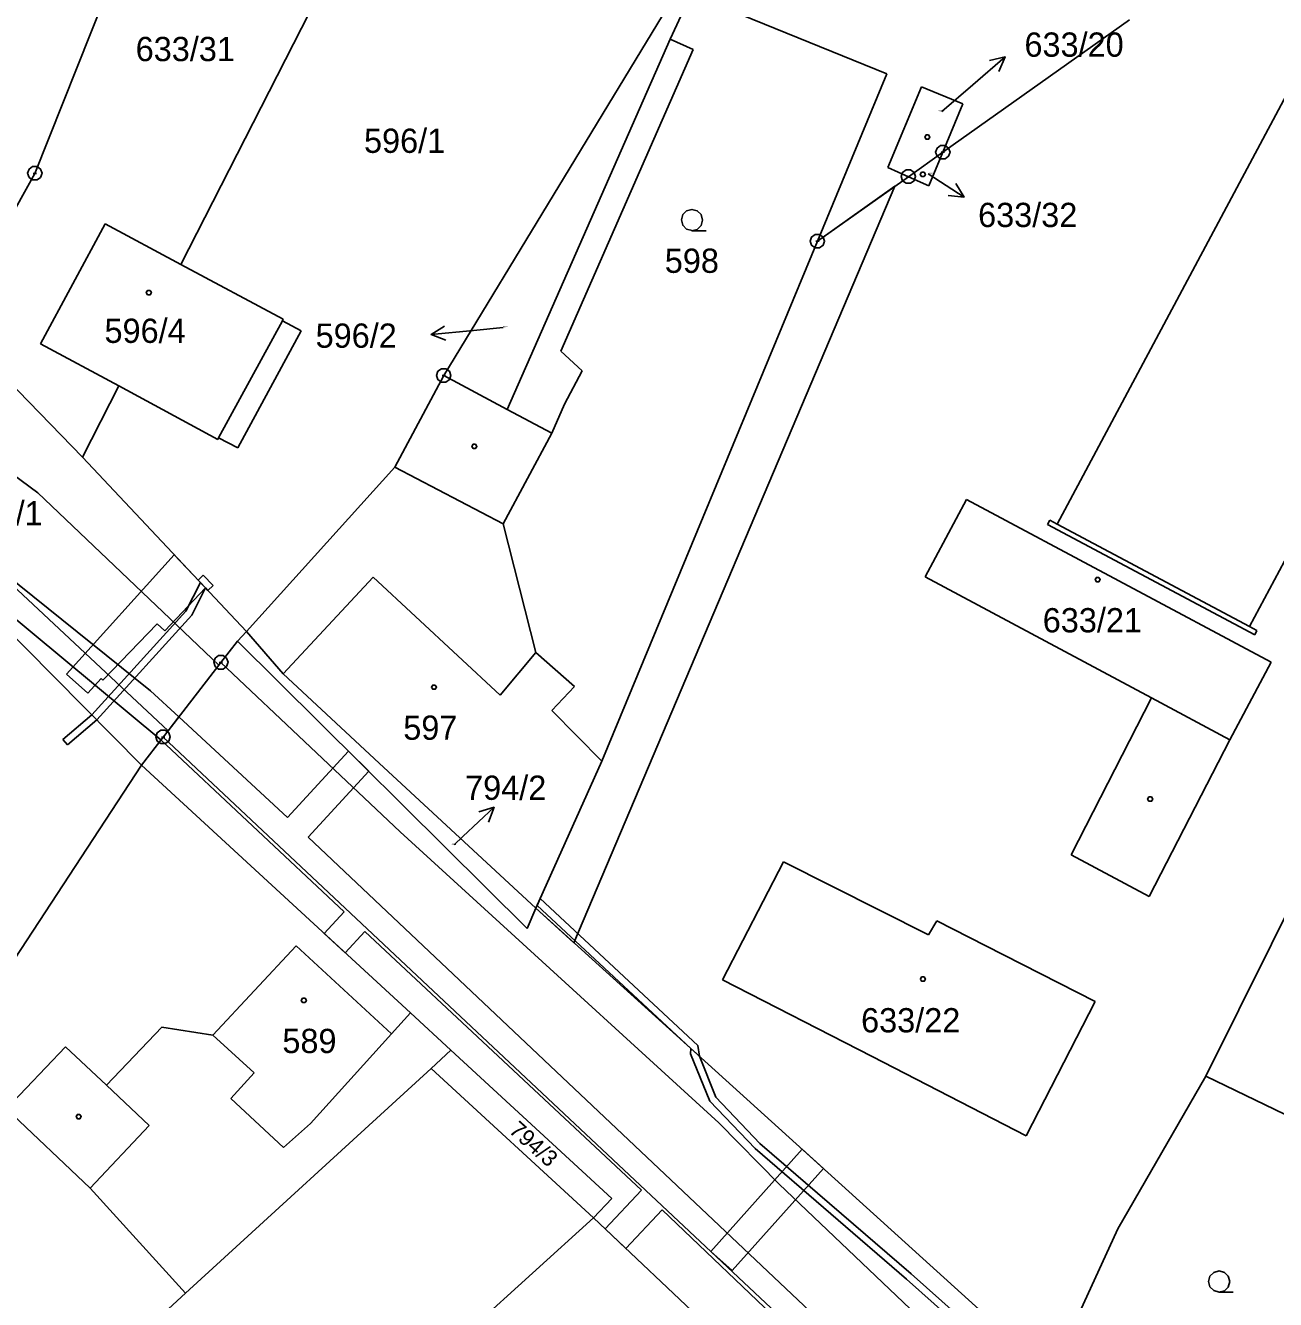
# Model space of a CAD drawing. Extents: x -759060 to -757386, y -1172273 to -1170948.
# Drawn here: x -758335.3 to -758247.7, y -1171458.9 to -1171369.6 of the extents above; entities that cross this region are included whole.
import ezdxf

# ---------------------------------------------------------------- set-up
doc = ezdxf.new("R2010")
doc.units = 0
for name, color, linetype in [('Vrstva 1', 7, 'Continuous'), ('Vrstva 12', 7, 'Continuous'), ('Vrstva 13', 7, 'Continuous'), ('Vrstva 2', 7, 'Continuous'), ('Vrstva 3', 7, 'Continuous'), ('Vrstva 4', 7, 'Continuous'), ('Vrstva 5', 7, 'Continuous'), ('Vrstva 7', 7, 'Continuous'), ('Vrstva 8', 7, 'Continuous')]:
    doc.layers.add(name, color=color, linetype=linetype)

msp = doc.modelspace()

# ---------------------------------------------------------------- linework, layer by layer
at = {"layer": 'Vrstva 1'}
for p, q in [((-758263.01, -1171404.59), (-758220.74, -1171325.36)), ((-758207.32, -1171332.5), (-758249.54, -1171411.77)), ((-758323.66, -1171352.29), (-758334.67, -1171380)), ((-758324.43, -1171386.38), (-758310.09, -1171358.28)), ((-758306.01, -1171394.17), (-758289.56, -1171367.06)), ((-758288.68, -1171367.44), (-758290.15, -1171370.6)), ((-758288.68, -1171367.44), (-758274.95, -1171373.03)), ((-758271.03, -1171378.52), (-758257.96, -1171369.23)), ((-758301.56, -1171396.55), (-758290.15, -1171370.6)), ((-758297.8, -1171392.45), (-758288.53, -1171371.32)), ((-758290.15, -1171370.6), (-758288.53, -1171371.32)), ((-758274.95, -1171373.03), (-758279.82, -1171384.76)), ((-758274.9, -1171379.58), (-758272.52, -1171373.92)), ((-758272.52, -1171373.92), (-758269.63, -1171375.13)), ((-758269.63, -1171375.13), (-758271.03, -1171378.52)), ((-758273.45, -1171380.23), (-758271.03, -1171378.52)), ((-758271.03, -1171378.52), (-758272.01, -1171380.88)), ((-758340.5, -1171390.47), (-758334.67, -1171380)), ((-758279.82, -1171384.76), (-758273.45, -1171380.23)), ((-758273.45, -1171380.23), (-758274.9, -1171379.58)), ((-758272.01, -1171380.88), (-758273.45, -1171380.23)), ((-758334.27, -1171391.95), (-758329.74, -1171383.54)), ((-758329.74, -1171383.54), (-758324.43, -1171386.38)), ((-758279.82, -1171384.76), (-758294.93, -1171421.2)), ((-758324.43, -1171386.38), (-758317.26, -1171390.22)), ((-758340.5, -1171390.47), (-758331.33, -1171399.89)), ((-758317.26, -1171390.22), (-758317.32, -1171390.33)), ((-758317.32, -1171390.33), (-758316, -1171391.03)), ((-758316, -1171391.03), (-758320.45, -1171399.24)), ((-758328.79, -1171394.9), (-758334.27, -1171391.95)), ((-758296.31, -1171393.84), (-758297.8, -1171392.45)), ((-758309.44, -1171400.58), (-758306.01, -1171394.17)), ((-758301.56, -1171396.55), (-758306.01, -1171394.17)), ((-758297.54, -1171396.18), (-758296.31, -1171393.84)), ((-758331.33, -1171399.89), (-758328.79, -1171394.9)), ((-758321.85, -1171398.64), (-758328.79, -1171394.9)), ((-758297.54, -1171396.18), (-758298.45, -1171398.21)), ((-758321.79, -1171398.53), (-758321.85, -1171398.64)), ((-758320.45, -1171399.24), (-758321.79, -1171398.53)), ((-758298.45, -1171398.21), (-758301.84, -1171404.57)), ((-758331.33, -1171399.89), (-758319.84, -1171412.11)), ((-758319.84, -1171412.11), (-758309.44, -1171400.58)), ((-758269.37, -1171402.85), (-758272.27, -1171408.28)), ((-758248.03, -1171414.27), (-758269.37, -1171402.85)), ((-758263.69, -1171404.6), (-758263.53, -1171404.31)), ((-758263.53, -1171404.31), (-758263.01, -1171404.59)), ((-758301.84, -1171404.57), (-758299.57, -1171413.59)), ((-758249.17, -1171412.34), (-758263.69, -1171404.6)), ((-758340.57, -1171407.96), (-758327.2, -1171421.47)), ((-758272.27, -1171408.28), (-758256.4, -1171416.77)), ((-758320.47, -1171412.78), (-758319.84, -1171412.11)), ((-758319.84, -1171412.11), (-758317.28, -1171415.08)), ((-758249.54, -1171411.77), (-758249.02, -1171412.05)), ((-758249.02, -1171412.05), (-758249.17, -1171412.34)), ((-758321.63, -1171414.28), (-758320.47, -1171412.78)), ((-758300.16, -1171432.92), (-758320.47, -1171412.78)), ((-758299.57, -1171413.59), (-758296.86, -1171415.96)), ((-758325.34, -1171419.07), (-758321.77, -1171414.46)), ((-758321.77, -1171414.46), (-758321.63, -1171414.28)), ((-758309.07, -1171426.15), (-758321.63, -1171414.28)), ((-758317.28, -1171415.08), (-758310.54, -1171421.35)), ((-758250.93, -1171419.7), (-758248.03, -1171414.27)), ((-758296.86, -1171415.96), (-758298.44, -1171417.64)), ((-758256.4, -1171416.77), (-758262.04, -1171427.76)), ((-758298.44, -1171417.64), (-758294.93, -1171421.2)), ((-758327.2, -1171421.47), (-758325.68, -1171419.51)), ((-758325.68, -1171419.51), (-758325.34, -1171419.07)), ((-758325.68, -1171419.51), (-758307.9, -1171436.22)), ((-758256.57, -1171430.68), (-758250.93, -1171419.7)), ((-758294.93, -1171421.2), (-758299.56, -1171431.51)), ((-758327.2, -1171421.47), (-758344.49, -1171447.89)), ((-758327.2, -1171421.47), (-758308.34, -1171438.85)), ((-758310.54, -1171421.35), (-758299.56, -1171431.51)), ((-758303.15, -1171431.56), (-758309.07, -1171426.15)), ((-758244.03, -1171426.01), (-758252.61, -1171443.29)), ((-758286.47, -1171436.53), (-758282.2, -1171428.25)), ((-758282.2, -1171428.25), (-758272.03, -1171433.38)), ((-758262.04, -1171427.76), (-758256.57, -1171430.68)), ((-758286.73, -1171446.54), (-758303.15, -1171431.56)), ((-758299.56, -1171431.51), (-758300.16, -1171432.92)), ((-758299.56, -1171431.51), (-758263.45, -1171464.18)), ((-758272.03, -1171433.38), (-758271.46, -1171432.39)), ((-758271.46, -1171432.39), (-758268.01, -1171434.15)), ((-758316.35, -1171434.14), (-758322.21, -1171440.4)), ((-758309.68, -1171440.3), (-758316.35, -1171434.14)), ((-758268.01, -1171434.15), (-758260.36, -1171438.05)), ((-758307.9, -1171436.22), (-758278, -1171464.29)), ((-758275.99, -1171441.91), (-758286.47, -1171436.53)), ((-758260.36, -1171438.05), (-758265.19, -1171447.47)), ((-758309.68, -1171440.3), (-758308.34, -1171438.85)), ((-758308.34, -1171438.85), (-758305.51, -1171441.46)), ((-758325.77, -1171439.84), (-758329.65, -1171443.92)), ((-758322.21, -1171440.4), (-758325.77, -1171439.84)), ((-758336.65, -1171445.58), (-758332.53, -1171441.22)), ((-758332.53, -1171441.22), (-758329.65, -1171443.92)), ((-758305.51, -1171441.46), (-758306.9, -1171442.74)), ((-758305.51, -1171441.46), (-758294.24, -1171451.85)), ((-758306.9, -1171442.74), (-758324.11, -1171458.49)), ((-758306.9, -1171442.74), (-758295.51, -1171453.22)), ((-758265.19, -1171447.47), (-758275.99, -1171441.91)), ((-758252.61, -1171443.29), (-758258.78, -1171453.97)), ((-758224.39, -1171456.86), (-758252.61, -1171443.29)), ((-758330.8, -1171451.14), (-758336.65, -1171445.58)), ((-758282.5, -1171450.86), (-758286.73, -1171446.54)), ((-758330.8, -1171451.14), (-758324.11, -1171458.49)), ((-758271.69, -1171461.13), (-758282.5, -1171450.86)), ((-758295.51, -1171453.22), (-758294.24, -1171451.85)), ((-758295.51, -1171453.22), (-758322.51, -1171477.63)), ((-758276.72, -1171470.98), (-758295.51, -1171453.22)), ((-758258.78, -1171453.97), (-758263.45, -1171464.18)), ((-758324.11, -1171458.49), (-758343.02, -1171475.78))]:
    msp.add_line(p, q, dxfattribs=at)
at = {"layer": 'Vrstva 12'}
for p, q in [((-758263.01, -1171404.59), (-758220.74, -1171325.36)), ((-758207.32, -1171332.5), (-758249.54, -1171411.77)), ((-758274.9, -1171379.58), (-758272.52, -1171373.92)), ((-758272.52, -1171373.92), (-758269.63, -1171375.13)), ((-758269.63, -1171375.13), (-758271.03, -1171378.52)), ((-758271.03, -1171378.52), (-758272.01, -1171380.88)), ((-758273.45, -1171380.23), (-758274.9, -1171379.58)), ((-758272.01, -1171380.88), (-758273.45, -1171380.23)), ((-758334.27, -1171391.95), (-758329.74, -1171383.54)), ((-758329.74, -1171383.54), (-758324.43, -1171386.38)), ((-758324.43, -1171386.38), (-758317.26, -1171390.22)), ((-758321.79, -1171398.53), (-758317.32, -1171390.33)), ((-758317.26, -1171390.22), (-758317.32, -1171390.33)), ((-758328.79, -1171394.9), (-758334.27, -1171391.95)), ((-758321.85, -1171398.64), (-758328.79, -1171394.9)), ((-758321.79, -1171398.53), (-758321.85, -1171398.64)), ((-758269.37, -1171402.85), (-758272.27, -1171408.28)), ((-758248.03, -1171414.27), (-758269.37, -1171402.85)), ((-758263.01, -1171404.59), (-758249.54, -1171411.77)), ((-758310.95, -1171408.29), (-758317.28, -1171415.08)), ((-758302.06, -1171416.57), (-758310.95, -1171408.29)), ((-758272.27, -1171408.28), (-758256.4, -1171416.77)), ((-758299.57, -1171413.59), (-758302.06, -1171416.57)), ((-758299.57, -1171413.59), (-758296.86, -1171415.96)), ((-758317.28, -1171415.08), (-758310.54, -1171421.35)), ((-758250.93, -1171419.7), (-758248.03, -1171414.27)), ((-758296.86, -1171415.96), (-758298.44, -1171417.64)), ((-758256.4, -1171416.77), (-758250.93, -1171419.7)), ((-758298.44, -1171417.64), (-758294.93, -1171421.2)), ((-758294.93, -1171421.2), (-758299.56, -1171431.51)), ((-758310.54, -1171421.35), (-758299.56, -1171431.51)), ((-758286.47, -1171436.53), (-758282.2, -1171428.25)), ((-758282.2, -1171428.25), (-758272.03, -1171433.38)), ((-758272.03, -1171433.38), (-758271.46, -1171432.39)), ((-758271.46, -1171432.39), (-758268.01, -1171434.15)), ((-758316.35, -1171434.14), (-758322.21, -1171440.4)), ((-758309.68, -1171440.3), (-758316.35, -1171434.14)), ((-758268.01, -1171434.15), (-758260.36, -1171438.05)), ((-758275.99, -1171441.91), (-758286.47, -1171436.53)), ((-758260.36, -1171438.05), (-758265.19, -1171447.47)), ((-758322.21, -1171440.4), (-758319.29, -1171443.05)), ((-758315.36, -1171446.6), (-758309.68, -1171440.3)), ((-758265.19, -1171447.47), (-758275.99, -1171441.91)), ((-758319.29, -1171443.05), (-758320.94, -1171444.84)), ((-758320.94, -1171444.84), (-758317.24, -1171448.28)), ((-758317.24, -1171448.28), (-758315.36, -1171446.6))]:
    msp.add_line(p, q, dxfattribs=at)
at = {"layer": 'Vrstva 13'}
for p, q in [((-758274.39, -1171380.9), (-758296.89, -1171433.93)), ((-758279.82, -1171384.76), (-758274.39, -1171380.9)), ((-758294.93, -1171421.2), (-758279.82, -1171384.76)), ((-758332.45, -1171415.1), (-758324.9, -1171406.73)), ((-758324.9, -1171406.73), (-758322.71, -1171409.06)), ((-758336.84, -1171407.99), (-758326.57, -1171416.28)), ((-758324.08, -1171410.68), (-758323.07, -1171408.67)), ((-758323.23, -1171408.5), (-758322.87, -1171408.16)), ((-758323.07, -1171408.67), (-758323.23, -1171408.5)), ((-758323.07, -1171408.67), (-758322.71, -1171409.06)), ((-758322.71, -1171409.06), (-758323.07, -1171408.67)), ((-758322.87, -1171408.16), (-758322.18, -1171408.89)), ((-758322.71, -1171409.06), (-758325.57, -1171412.07)), ((-758322.71, -1171409.06), (-758323.66, -1171410.96)), ((-758322.55, -1171409.23), (-758322.71, -1171409.06)), ((-758322.18, -1171408.89), (-758322.55, -1171409.23)), ((-758325.84, -1171419.71), (-758337.25, -1171410.23)), ((-758330.69, -1171417.95), (-758324.08, -1171410.68)), ((-758323.66, -1171410.96), (-758330.34, -1171418.3)), ((-758326.1, -1171411.58), (-758329.9, -1171415.52)), ((-758325.57, -1171412.07), (-758326.1, -1171411.58)), ((-758330.97, -1171416.44), (-758332.45, -1171415.1)), ((-758330.02, -1171415.4), (-758330.97, -1171416.44)), ((-758329.9, -1171415.52), (-758330.02, -1171415.4)), ((-758326.57, -1171416.28), (-758324.59, -1171418.1)), ((-758332.7, -1171419.67), (-758330.69, -1171417.95)), ((-758330.34, -1171418.3), (-758332.38, -1171420.05)), ((-758330.69, -1171417.95), (-758330.34, -1171418.3)), ((-758330.34, -1171418.3), (-758330.69, -1171417.95)), ((-758324.59, -1171418.1), (-758325.34, -1171419.07)), ((-758325.34, -1171419.07), (-758324.59, -1171418.1)), ((-758324.59, -1171418.1), (-758316.97, -1171425.14)), ((-758325.68, -1171419.51), (-758325.84, -1171419.71)), ((-758325.84, -1171419.71), (-758325.68, -1171419.51)), ((-758325.34, -1171419.07), (-758325.68, -1171419.51)), ((-758325.68, -1171419.51), (-758325.34, -1171419.07)), ((-758332.38, -1171420.05), (-758332.7, -1171419.67)), ((-758312.99, -1171431.76), (-758325.84, -1171419.71)), ((-758316.97, -1171425.14), (-758312.7, -1171420.49)), ((-758312.7, -1171420.49), (-758311.27, -1171421.9)), ((-758299.56, -1171431.51), (-758294.93, -1171421.2)), ((-758311.27, -1171421.9), (-758315.52, -1171426.52)), ((-758315.52, -1171426.52), (-758269.89, -1171469.64)), ((-758299.47, -1171431.31), (-758299.26, -1171430.83)), ((-758299.26, -1171430.83), (-758288.2, -1171441.14)), ((-758314.39, -1171433.27), (-758312.99, -1171431.76)), ((-758296.89, -1171433.93), (-758299.56, -1171431.51)), ((-758288.7, -1171441.34), (-758299.47, -1171431.31)), ((-758312.92, -1171434.63), (-758314.39, -1171433.27)), ((-758311.54, -1171433.14), (-758312.92, -1171434.63)), ((-758292.16, -1171451.28), (-758311.54, -1171433.14)), ((-758288.71, -1171441.71), (-758288.7, -1171441.34)), ((-758287.37, -1171445.02), (-758288.71, -1171441.71)), ((-758288.7, -1171441.34), (-758288.1, -1171441.88)), ((-758288.1, -1171441.88), (-758288.7, -1171441.34)), ((-758288.2, -1171441.14), (-758288.1, -1171441.88)), ((-758288.1, -1171441.88), (-758286.95, -1171444.74)), ((-758284.19, -1171448.36), (-758287.37, -1171445.02)), ((-758286.95, -1171444.74), (-758283.85, -1171448)), ((-758283.85, -1171448), (-758273.25, -1171457.14)), ((-758287.3, -1171455.57), (-758280.9, -1171448.4)), ((-758273.57, -1171457.52), (-758284.19, -1171448.36)), ((-758280.9, -1171448.4), (-758279.4, -1171449.75)), ((-758279.4, -1171449.75), (-758285.81, -1171456.9)), ((-758294.7, -1171453.98), (-758292.16, -1171451.28)), ((-758290.71, -1171452.65), (-758293.25, -1171455.36)), ((-758272.54, -1171469.97), (-758290.71, -1171452.65)), ((-758293.25, -1171455.36), (-758294.7, -1171453.98)), ((-758285.81, -1171456.9), (-758287.3, -1171455.57)), ((-758264.65, -1171465.43), (-758273.57, -1171457.52)), ((-758273.25, -1171457.14), (-758264.31, -1171465.07))]:
    msp.add_line(p, q, dxfattribs=at)
at = {"layer": 'Vrstva 3'}
for points in [[(-758288.61, -1171384), (-758288.99, -1171383.9), (-758289.26, -1171383.63), (-758289.36, -1171383.26), (-758289.26, -1171382.89), (-758288.99, -1171382.62), (-758288.62, -1171382.52), (-758288.25, -1171382.62), (-758287.98, -1171382.89), (-758287.88, -1171383.27), (-758287.98, -1171383.65), (-758288.25, -1171383.92), (-758288.63, -1171384.02), (-758287.63, -1171384.02)], [(-758251.66, -1171458.41), (-758252.04, -1171458.31), (-758252.31, -1171458.04), (-758252.41, -1171457.67), (-758252.31, -1171457.3), (-758252.04, -1171457.03), (-758251.67, -1171456.93), (-758251.3, -1171457.03), (-758251.03, -1171457.3), (-758250.93, -1171457.68), (-758251.03, -1171458.06), (-758251.3, -1171458.33), (-758251.68, -1171458.43), (-758250.68, -1171458.43)]]:
    msp.add_lwpolyline(points, dxfattribs=at)
at = {"layer": 'Vrstva 4'}
for p, q in [((-758321.79, -1171398.53), (-758317.32, -1171390.33)), ((-758334.46, -1171402.39), (-758348.96, -1171391.71)), ((-758298.45, -1171398.21), (-758301.56, -1171396.55)), ((-758309.44, -1171400.58), (-758301.84, -1171404.57)), ((-758321.77, -1171414.46), (-758334.46, -1171402.39)), ((-758263.01, -1171404.59), (-758249.54, -1171411.77)), ((-758338.57, -1171406.69), (-758325.34, -1171419.07)), ((-758310.95, -1171408.29), (-758317.28, -1171415.08)), ((-758302.06, -1171416.57), (-758310.95, -1171408.29)), ((-758299.57, -1171413.59), (-758302.06, -1171416.57)), ((-758256.4, -1171416.77), (-758250.93, -1171419.7)), ((-758322.21, -1171440.4), (-758319.29, -1171443.05)), ((-758315.36, -1171446.6), (-758309.68, -1171440.3)), ((-758319.29, -1171443.05), (-758320.94, -1171444.84)), ((-758329.65, -1171443.92), (-758326.65, -1171446.74)), ((-758320.94, -1171444.84), (-758317.24, -1171448.28)), ((-758326.65, -1171446.74), (-758330.8, -1171451.14)), ((-758317.24, -1171448.28), (-758315.36, -1171446.6))]:
    msp.add_line(p, q, dxfattribs=at)
at = {"layer": 'Vrstva 5'}
for points in [[(-758272.03, -1171377.3), (-758271.94, -1171377.45), (-758272.03, -1171377.6), (-758272.21, -1171377.6), (-758272.3, -1171377.45), (-758272.21, -1171377.3)], [(-758272.35, -1171379.92), (-758272.26, -1171380.07), (-758272.35, -1171380.22), (-758272.53, -1171380.22), (-758272.62, -1171380.07), (-758272.53, -1171379.92)], [(-758326.59, -1171388.2), (-758326.5, -1171388.35), (-758326.59, -1171388.5), (-758326.77, -1171388.5), (-758326.86, -1171388.35), (-758326.77, -1171388.2)], [(-758303.78, -1171398.98), (-758303.69, -1171399.13), (-758303.78, -1171399.28), (-758303.96, -1171399.28), (-758304.05, -1171399.13), (-758303.96, -1171398.98)], [(-758260.09, -1171408.32), (-758260, -1171408.47), (-758260.09, -1171408.62), (-758260.27, -1171408.62), (-758260.36, -1171408.47), (-758260.27, -1171408.32)], [(-758306.61, -1171415.86), (-758306.52, -1171416.01), (-758306.61, -1171416.16), (-758306.79, -1171416.16), (-758306.88, -1171416.01), (-758306.79, -1171415.86)], [(-758256.41, -1171423.71), (-758256.32, -1171423.86), (-758256.41, -1171424.01), (-758256.59, -1171424.01), (-758256.68, -1171423.86), (-758256.59, -1171423.71)], [(-758272.34, -1171436.32), (-758272.25, -1171436.47), (-758272.34, -1171436.62), (-758272.52, -1171436.62), (-758272.61, -1171436.47), (-758272.52, -1171436.32)], [(-758315.73, -1171437.82), (-758315.64, -1171437.97), (-758315.73, -1171438.12), (-758315.91, -1171438.12), (-758316, -1171437.97), (-758315.91, -1171437.82)], [(-758331.51, -1171445.96), (-758331.42, -1171446.11), (-758331.51, -1171446.26), (-758331.69, -1171446.26), (-758331.78, -1171446.11), (-758331.69, -1171445.96)]]:
    msp.add_lwpolyline(points, close=True, dxfattribs=at)
at = {"layer": 'Vrstva 7'}
for p, q in [((-758266.67, -1171371.819), (-758268.94, -1171373.78)), ((-758271.11, -1171375.66), (-758268.94, -1171373.78)), ((-758269.543, -1171381.657), (-758272.07, -1171380.04)), ((-758301.86, -1171390.8), (-758303.92, -1171391)), ((-758306.906, -1171391.291), (-758303.92, -1171391)), ((-758302.491, -1171424.428), (-758304.67, -1171426.49)), ((-758305.29, -1171427.07), (-758304.67, -1171426.49))]:
    msp.add_line(p, q, dxfattribs=at)
for points in [[(-758267.754, -1171372.094), (-758266.67, -1171371.819), (-758267.1, -1171372.851)], [(-758270.116, -1171380.697), (-758269.543, -1171381.657), (-758270.655, -1171381.539)], [(-758305.862, -1171391.692), (-758306.906, -1171391.291), (-758305.959, -1171390.696)], [(-758303.561, -1171424.752), (-758302.491, -1171424.428), (-758302.873, -1171425.479)]]:
    msp.add_lwpolyline(points, dxfattribs=at)
at = {"layer": 'Vrstva 8'}
for p, q in [((-758271.15, -1171378.52), (-758270.91, -1171378.52)), ((-758334.79, -1171380), (-758334.55, -1171380)), ((-758273.57, -1171380.23), (-758273.33, -1171380.23)), ((-758279.94, -1171384.76), (-758279.7, -1171384.76)), ((-758306.13, -1171394.17), (-758305.89, -1171394.17)), ((-758321.75, -1171414.28), (-758321.51, -1171414.28)), ((-758325.8, -1171419.51), (-758325.56, -1171419.51))]:
    msp.add_line(p, q, dxfattribs=at)
for points in [[(-758270.88, -1171378.04), (-758270.63, -1171378.22), (-758270.53, -1171378.51), (-758270.63, -1171378.8), (-758270.88, -1171378.98), (-758271.19, -1171378.98), (-758271.44, -1171378.8), (-758271.54, -1171378.51), (-758271.44, -1171378.22), (-758271.19, -1171378.04)], [(-758334.52, -1171379.52), (-758334.27, -1171379.7), (-758334.17, -1171379.99), (-758334.27, -1171380.28), (-758334.52, -1171380.46), (-758334.83, -1171380.46), (-758335.08, -1171380.28), (-758335.18, -1171379.99), (-758335.08, -1171379.7), (-758334.83, -1171379.52)], [(-758273.3, -1171379.75), (-758273.05, -1171379.93), (-758272.95, -1171380.22), (-758273.05, -1171380.51), (-758273.3, -1171380.69), (-758273.61, -1171380.69), (-758273.86, -1171380.51), (-758273.96, -1171380.22), (-758273.86, -1171379.93), (-758273.61, -1171379.75)], [(-758279.67, -1171384.28), (-758279.42, -1171384.46), (-758279.32, -1171384.75), (-758279.42, -1171385.04), (-758279.67, -1171385.22), (-758279.98, -1171385.22), (-758280.23, -1171385.04), (-758280.33, -1171384.75), (-758280.23, -1171384.46), (-758279.98, -1171384.28)], [(-758305.86, -1171393.69), (-758305.61, -1171393.87), (-758305.51, -1171394.16), (-758305.61, -1171394.45), (-758305.86, -1171394.63), (-758306.17, -1171394.63), (-758306.42, -1171394.45), (-758306.52, -1171394.16), (-758306.42, -1171393.87), (-758306.17, -1171393.69)], [(-758321.48, -1171413.8), (-758321.23, -1171413.98), (-758321.13, -1171414.27), (-758321.23, -1171414.56), (-758321.48, -1171414.74), (-758321.79, -1171414.74), (-758322.04, -1171414.56), (-758322.14, -1171414.27), (-758322.04, -1171413.98), (-758321.79, -1171413.8)], [(-758325.53, -1171419.03), (-758325.28, -1171419.21), (-758325.18, -1171419.5), (-758325.28, -1171419.79), (-758325.53, -1171419.97), (-758325.84, -1171419.97), (-758326.09, -1171419.79), (-758326.19, -1171419.5), (-758326.09, -1171419.21), (-758325.84, -1171419.03)]]:
    msp.add_lwpolyline(points, close=True, dxfattribs=at)

# ---------------------------------------------------------------- texts
at = {"layer": 'Vrstva 2'}
for s, height, p in [('633/31', 1.7, (-758327.606, -1171372.13)), ('633/20', 0.1, (-758271.369, -1171375.66)), ('596/1', 1.7, (-758311.602, -1171378.56)), ('633/32', 0.1, (-758272.049, -1171380.04)), ('598', 1.7, (-758290.521, -1171386.97)), ('596/4', 1.7, (-758329.79, -1171391.88)), ('596/2', 0.1, (-758301.846, -1171390.8)), ('794/1', 1.7, (-758339.813, -1171404.67)), ('633/21', 1.7, (-758264.032, -1171412.17)), ('597', 1.7, (-758308.851, -1171419.7)), ('794/2', 0.1, (-758305.494, -1171427.07)), ('633/22', 1.7, (-758276.764, -1171440.21)), ('589', 1.7, (-758317.323, -1171441.66))]:
    msp.add_text(s, height=height, dxfattribs=at).set_placement(p)
msp.add_text('794/3', height=1.14, rotation=318.22076, dxfattribs=at).set_placement((-758301.511, -1171447.176))
at = {"layer": 'Vrstva 7'}
for s, p in [('633/20', (-758265.313, -1171371.82)), ('633/32', (-758268.563, -1171383.76)), ('596/2', (-758314.995, -1171392.22)), ('794/2', (-758304.517, -1171423.91))]:
    msp.add_text(s, height=1.7, dxfattribs=at).set_placement(p)

doc.saveas('drawing.dxf')
